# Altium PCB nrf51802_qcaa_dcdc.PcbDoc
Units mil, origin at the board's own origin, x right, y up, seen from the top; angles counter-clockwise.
Board outline 582.37 x 541 mil, 2 copper layers (Top Layer, Bottom Layer), stack 62.441 mil thick; 22 components, 32 nets, 78 pads, 39 vias.
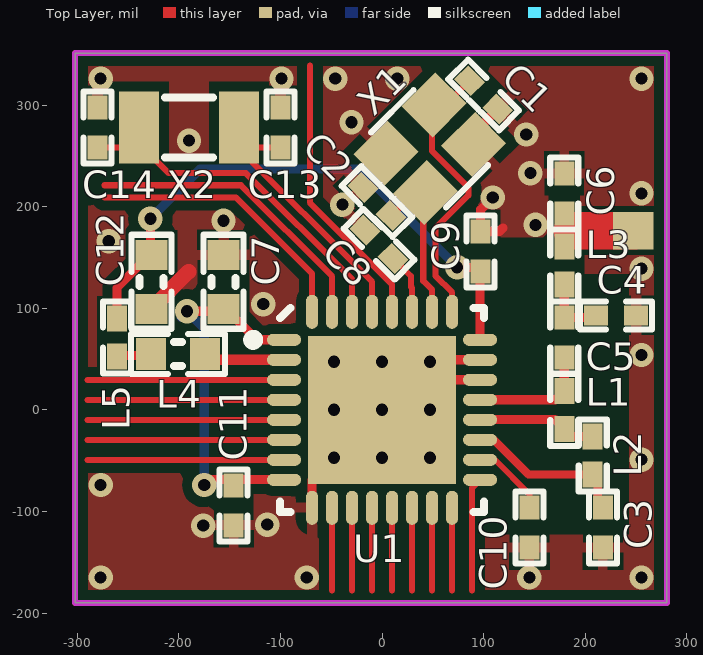
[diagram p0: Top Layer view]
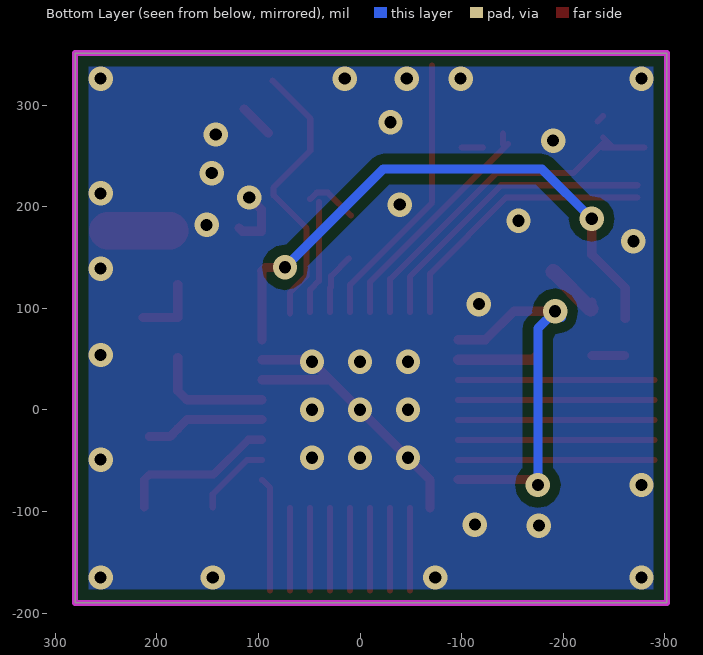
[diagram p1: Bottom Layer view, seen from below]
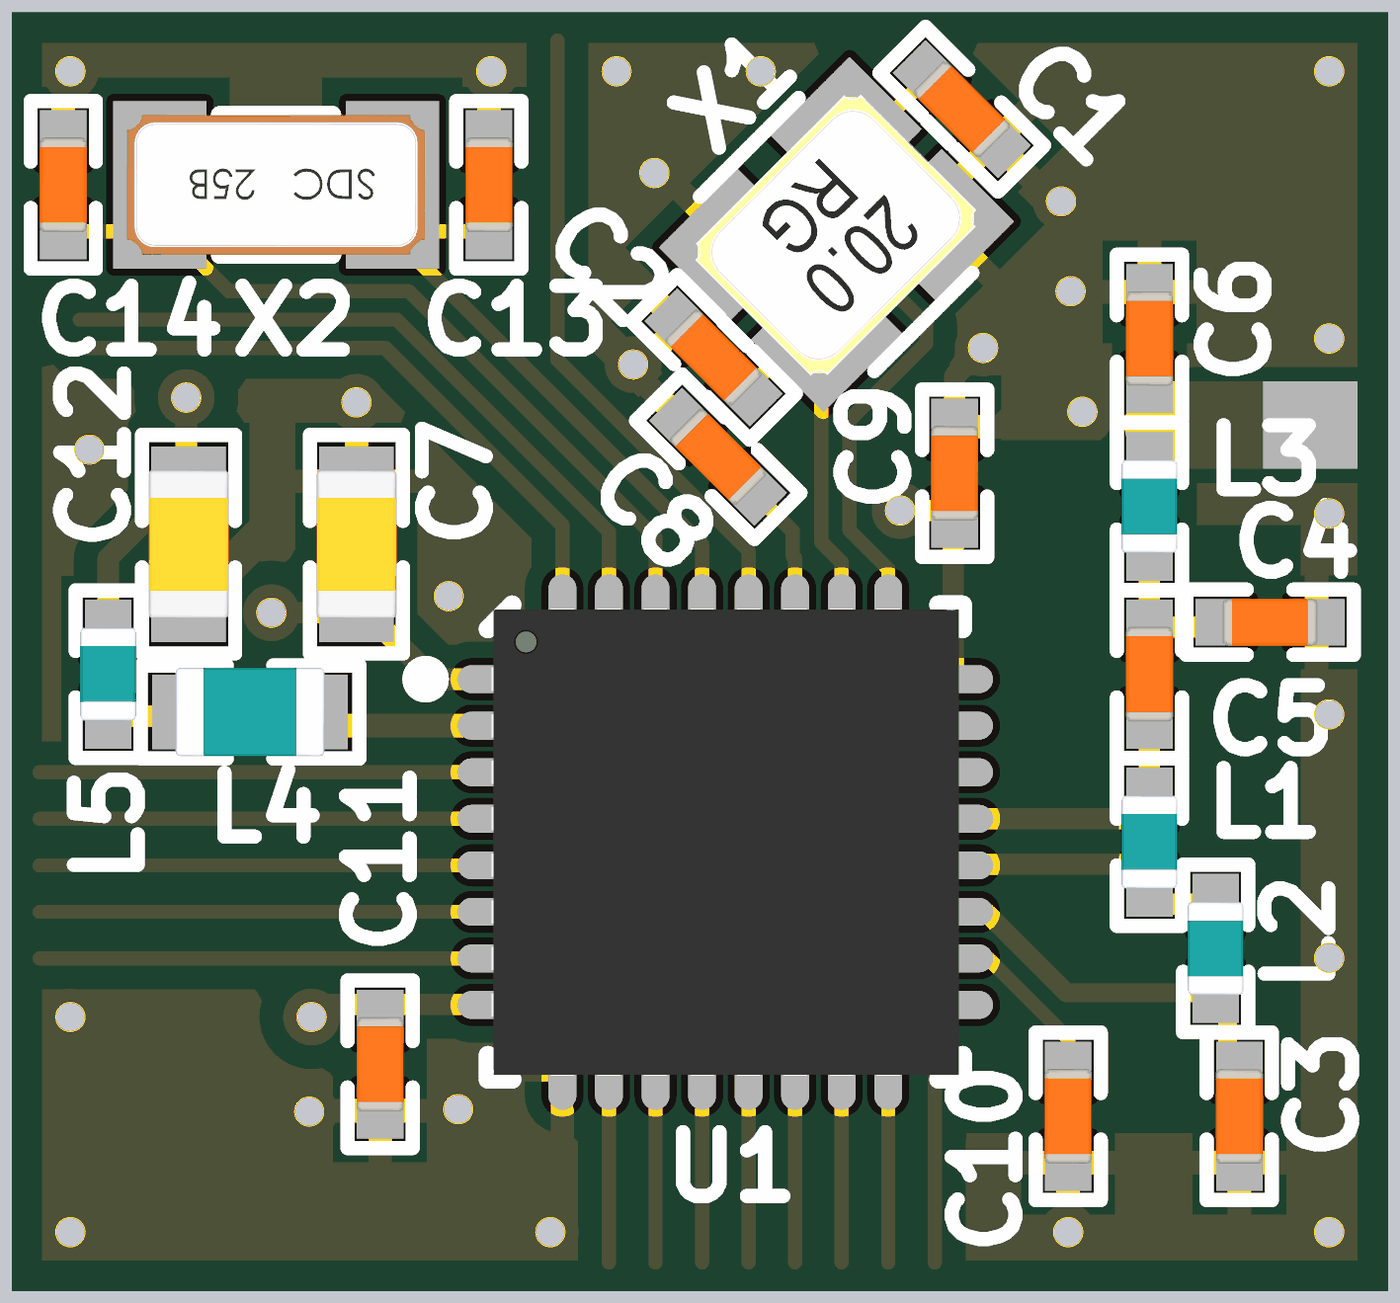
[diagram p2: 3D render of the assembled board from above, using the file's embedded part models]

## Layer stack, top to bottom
Top Solder: solder mask 0.4, Solder Resist, Dk 3.5
Top Layer: signal copper 0.7087
Dielectric1: core 61.0236, FR-4, Dk 4.8
Bottom Layer: signal copper 0.7087
Bottom Solder: solder mask 0.4, Solder Resist, Dk 3.5

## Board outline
-302,-190 280.37,-190 280.37,351 -302,351

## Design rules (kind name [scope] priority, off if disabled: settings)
Clearance Polygon_ANT [(InNamedPolygon('Top_Layer-GND')) or (InNamedPolygon('Bottom_Layer-GND')) vs InNet('NetC6_1')] p1: gap=6
Clearance Polygon [(InNamedPolygon('Top_Layer-GND')) or (InNamedPolygon('Bottom_Layer-GND'))] p2: gap=10
Clearance [All] p3: gap=6
ComponentClearance [All] p1 off: gap=10 collisioncheckmode=3 verticalgap=10 showdistances=FALSE
FabricationTestPointUsage TestPointUsage [All] p1: valid=0 allowmultiple=FALSE
FabricationTestpoint Testpoint [All] p1: side=3 testpointundercomponent=TRUE minsize=40 maxsize=100 preferedsize=60 minholesize=0 maxholesize=40 preferedholesize=32 testpointgrid=1 allowsidetop=TRUE allowsidebottom=TRUE usegrid=TRUE gridtolerance=0.01
Height [All] p1 off: minheight=0 maxheight=1000 prefheight=500
HoleSize [All] p1: absolutevalues=TRUE maxlimit=160 minlimit=12 maxpercent=80.000 minpercent=20.000
MinimumAnnularRing [All] p1 off: minimumring=6
PolygonConnect PolygonConnect_1 [isVia and innet(gnd)] p1: connectstyle=Direct reliefconductorwidth=10 reliefentries=4 polygonreliefangle="90 Angle" airgapwidth=10
PolygonConnect [All] p2: connectstyle=Relief reliefconductorwidth=10 reliefentries=4 polygonreliefangle="90 Angle" airgapwidth=10
RoutingVias [All] p1: holewidth=12 width=24 viastyle="Through Hole" minholewidth=12 minwidth=24 maxholewidth=28 maxwidth=50
SilkToSolderMaskClearance SilkscreenOverComponentPads [IsPad] p1: minsilkscreentomaskgap=10 clearancetoexposedcopper=TRUE
SolderMaskExpansion [All] p1: expansion=3
Width [All] p1: maxlimit=100 minlimit=6 preferedwidth=6
24 further rules are at their usual default settings.

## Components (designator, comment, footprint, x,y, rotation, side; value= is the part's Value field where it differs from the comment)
C1 "12pF" CAPC1005X04L 100,310 r315 top (schematic designator C7)
C2 "12pF" CAPC1005X04L -5,205 r135 top
C3 "2.2nF" CAPC1005X04L 217.37,-116 r270 top
C4 "1.0pF" CAPC1005X04L 230.37,93 r0 top
C5 "3.9pF" CAPC1005X04L 179.37,71 r90 top
C6 "1.5pF" CAPC1005X04L 179.37,213 r90 top
C7 "4.7µF" CAPC1608X06L -156,126 r90 top (schematic designator C9)
C8 "100nF" CAPC1005X04L -3,163 r135 top (schematic designator C10)
C9 "1.0nF" CAPC1005X04L 97,156 r90 top (schematic designator C8)
C10 "47nF" CAPC1005X04L 145,-116 r270 top (schematic designator C11)
C11 "100nF" CAPC1005X04L -146,-94 r270 top (schematic designator C12)
C12 "1.0µF" CAPC1608X06L -227,126 r90 top (schematic designator C11)
C13 "12pF" CAPC1005X04L -100,278 r270 top
C14 "12pF" CAPC1005X04L -280,278 r270 top
L1 "5.6nH" INDC1005X04L 179.37,0 r90 top
L2 "10nH" INDC1005X04L 207.37,-45 r90 top
L3 "2.7nH" INDC1005X04L 179.37,142 r90 top
L4 "10µH" INDC1608X06L -201,55 r180 top (schematic designator L5)
L5 "15nH" INDC1005X04L -261,71 r90 top (schematic designator L6)
U1 "nRF51802-QCAA" Nordic_QFN50P500X500X90-33N 0,0 r0 top
X1 "16MHz" BT-XTAL_2520 47,257 r225 top
X2 "32.768kHz" XTAL_3215 -190,278 r180 top

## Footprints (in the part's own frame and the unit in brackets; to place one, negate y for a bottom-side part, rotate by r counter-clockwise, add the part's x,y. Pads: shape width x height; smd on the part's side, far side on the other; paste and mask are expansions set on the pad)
BT-XTAL_2520 [mm] "TSX-2520"
  rect 1.2x1.1 smd: 1(-0.85,-0.7) 2(0.85,-0.7) 3(0.85,0.7) 4(-0.85,0.7)
  silkscreen extent -1.55,-1.33 1.53,1.32, body extent -1.25,-1 1.27,1, height 0.56
CAPC1005X04L [mm] "Chip Capacitor, 2-Leads, Body 1.0x0.5mm, IPC High Density"
  rect 0.6x0.5 smd: 1(-0.5,0) 2(0.5,0)
  silkscreen extent -0.9,-0.35 0.9,0.35, body extent -0.51,-0.25 0.51,0.25, height 0.5
CAPC1608X06L [mm] "Chip Capacitor, 2-Leads, Body 1.6x0.8mm, IPC High Density"
  rect 0.75x0.8 smd: 1(-0.675,0) 2(0.675,0)
  silkscreen extent -1.17,-0.5 1.17,0.5, body extent -0.8,-0.43 0.8,0.43, height 0.8
INDC1005X04L [mm] "Chip Inductor, 2-Leads, Body 1.0x0.5mm, IPC High Density"
  rect 0.65x0.5 smd: 1(-0.475,0) 2(0.475,0)
  silkscreen extent -0.9,-0.35 0.9,0.35, body extent -0.5,-0.3 0.5,0.3, height 0.5
INDC1608X06L [mm] "Chip Inductor, 2-Leads, Body 1.6x0.8mm, IPC High Density"
  rect 0.75x0.8 smd: 1(-0.675,0) 2(0.675,0)
  silkscreen extent -1.17,-0.5 1.17,0.5, body extent -0.8,-0.48 0.8,0.48, height 0.8
Nordic_QFN50P500X500X90-33N [mm] "QFN32 5x5x0.85mm, 0.5mm pitch - Medium Density"
  oval 0.85x0.3 smd mask+0.076: 1(-2.45,1.75) 2(-2.45,1.25) 3(-2.45,0.75) 4(-2.45,0.25) 5(-2.45,-0.25) 6(-2.45,-0.75) 7(-2.45,-1.25) 8(-2.45,-1.75) 17(2.45,-1.75) 18(2.45,-1.25) 19(2.45,-0.75) 20(2.45,-0.25) 21(2.45,0.25) 22(2.45,0.75) 23(2.45,1.25) 24(2.45,1.75)
  oval 0.3x0.85 smd mask+0.076: 9(-1.75,-2.45) 10(-1.25,-2.45) 11(-0.75,-2.45) 12(-0.25,-2.45) 13(0.25,-2.45) 14(0.75,-2.45) 15(1.25,-2.45) 16(1.75,-2.45) 25(1.75,2.45) 26(1.25,2.45) 27(0.75,2.45) 28(0.25,2.45) 29(-0.25,2.45) 30(-0.75,2.45) 31(-1.25,2.45) 32(-1.75,2.45)
  rect 3.7x3.7 smd mask+0: 33(0,0)
  silkscreen extent -3.34,-2.55 2.55,2.55, body extent -2.51,-2.51 2.51,2.51, height 0.8
XTAL_3215 [mm] "XTAL SMD 3.2 x 1.5 mm"
  rect 1x1.8 smd: 1(-1.25,0) 2(1.25,0)
  silkscreen extent -0.6,-0.75 0.6,0.75, body extent -1.6,-0.75 1.6,0.75, height 0.81

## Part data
C1 C2 C13 C14: library part C0402-12p, "Capacitor, NP0, ±2%"
C3: library part C0402-2n2, "Capacitor, X7R, ±10%"
C4: library part C0402-1.0p, "Capacitor, NP0, ±0.1pF"
C5: library part C0402-3.9p, "Capacitor, NP0, ±0.1pF"
C6: library part C0402-1.5p, "Capacitor, NP0, ±0.1pF"
C7: library part C0603-4µ7, "Capacitor, X5R, ±10%"
C8 C11: library part C0402-100n, "Capacitor, X7R, ±10%"
C9: library part C0402-1n0, "Capacitor, X7R, ±10%"
C10: library part C0402-47n, "Capacitor, X7R, ±10%"
C12: library part C0603-1µ0, "Capacitor, X7R, ±10%"
L1: library part L0402-5n6, "High frequency chip inductor ±5%"
L2: library part L0402-10n, "High frequency chip inductor ±5%"
L3: library part L0402-2n7, "Inductor, 220mA, ±0.1nH"
L4: library part L0603-10µ, "Chip inductor, IDC,min = 50 mA, ±20%"
L5: library part L0402-15n, "High frequency chip inductor ±10%"
U1: "Multi-protocol Bluetooth Low Energy and 2.4GHz proprietary system-on-chip"
X1: library part XTAL_SMD2520_16MHz_8pF_NDK, "XTAL SMD 2520, 16MHz, 8pF, ±40ppm"
X2: library part "XTAL_FC-135 32.768k", "XTAL SMD 3215, 32.768kHz, 9pF, ±20ppm"

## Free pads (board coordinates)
  rect 40x37 smd: 0(247.37,176.43)

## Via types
v1: diameter 24, hole 12, Top Layer to Bottom Layer, tented both sides, 30 vias
v2: diameter 24, hole 12, Top Layer to Bottom Layer, tented bottom, 9 vias

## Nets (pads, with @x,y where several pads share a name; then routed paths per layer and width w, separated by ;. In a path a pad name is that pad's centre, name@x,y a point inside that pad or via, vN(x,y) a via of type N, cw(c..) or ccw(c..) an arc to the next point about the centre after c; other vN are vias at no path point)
AVDD: C9.1 C12.2 L5.2 U1.24 | length 566.6
  Top Layer w9: L5.2 -261,120 -228,153 v1(-228,188) ; v1(73.91,140.24) 93.07,140.24 C9.1 96.46,135.77 U1.24
  Bottom Layer w9: v1(-228,188) -179,237 -22.85,237 v1(73.91,140.24)
GND: C1.2 C2.2 C3.2 C4.2 C6.2 C7.2 C8.2 C9.2 C10.2 C11.2 C12.1 C13.1 C14.1 U1.9 U1.22 U1.23 U1.33 X1.2 X1.4 | length 463.2
  Top Layer w9: C12.1@-228,99 C12.1@-228,106 ; U1.9 -68.9,-68.9 v2(-47.24,-47.24) v2(0,0) U1.33@29.53,29.53 ; X1.4@90.15,272.31 C1.2 ; U1.22 U1.33@29.53,29.53 ; U1.23 49.21,49.21 v2(47.24,47.24) U1.33@29.53,29.53 ; v1(109,209) 97,197 C9.2 115.69,175.69 119,179
  Top Layer w15: C12.1 -190.43,136 -190,136
  other v1: -277,-165 -74,-165 145,-165 255.37,-165 -176,-114 -113,-113 -277,-74 255.37,-49 255.37,54 -117,104 255.37,139 -269,166 151,182 -156,186 -39,202 255.37,213 146,233 -190,265 142,271 -30,283 -277,326 -99,326 -46,326 15,326 255.37,326
  other v2: 0,-47.24 47.24,-47.24 -47.24,0 47.24,0 -47.24,47.24 0,47.24
NetC1_1: C1.1 U1.25 X1.1 | length 279.4
  Top Layer w6: U1.25 68.9,115.55 52.53,131.92 52.53,178.53 85,211 85,219 49,255 49,286.84 C1.1 ; U1.25@69,95 U1.25@69,96.46
NetC2_1: C2.1 U1.26 X1.3 | length 164.1
  Top Layer w6: C2.1 31.69,213.85 X1.3 X1.3@49.21,207.46 ; X1.3@40.53,204.61 40.53,126.95 49.21,118.27 U1.26
NetC3_1: C3.1 L2.1 U1.19 | length 159.8
  Top Layer w8: U1.19 110.09,-29.53 144.27,-63.7 L2.1 212.37,-68.7 C3.1@212.37,-96.31
NetC4_1: C4.1 C5.2 L3.1 | length 66.6
  Top Layer w9: C5.2 L3.1 ; C5.2@179.68,91 C4.1@213.68,91
NetC5_1: C5.1 L1.2 U1.21 | length 119.2
  Top Layer w9: U1.21 170.51,9.84 L1.2 C5.1
NetC6_1: C6.1 L3.2 pad.0 | length 61
  Top Layer w37: 187.37,176.43 pad.0@248.37,176.43
NetC8_1: C8.1 U1.27 | length 60.3
  Top Layer w6: C8.1 28.53,131.47 28.53,121 29.53,120 U1.27
NetC10_1: C10.1 U1.18 | length 75.9
  Top Layer w6: U1.18 111.21,-49.21 145,-83 C10.1
NetL1_1: L1.1 L2.2 U1.20 | length 117.9
  Top Layer w9: U1.20@96.46,-9.37 170.04,-9.37 L1.1 186.97,-26.3 L2.2
NetL4_1: L4.1 U1.2 | length 79.1
  Top Layer w10: L4.1@-174,53 -170.21,49.21 U1.2
NetL4_2: L4.2 L5.1 | length 31.7
  Top Layer w9: L5.1@-259.98,53.32 L4.2@-228.32,53.32
P0.00: U1.3 | length 193.5
  Top Layer w6: -290,29.53 U1.3
P0.02: U1.4 | length 193.5
  Top Layer w6: -290,9.84 U1.4
P0.03: U1.5 | length 193.5
  Top Layer w6: -290,-9.84 U1.5
P0.04: U1.6 | length 193.5
  Top Layer w6: -290,-29.53 U1.6
P0.06: U1.7 | length 193.5
  Top Layer w6: -290,-49.21 U1.7
P0.08: U1.10 | length 81.4
  Top Layer w6: -49.21,-177.81 U1.10
P0.09: U1.11 | length 81.4
  Top Layer w6: -29.53,-177.81 U1.11
P0.12: U1.12 | length 81.4
  Top Layer w6: -9.84,-177.81 U1.12
P0.14: U1.13 | length 81.4
  Top Layer w6: 9.84,-177.81 U1.13
P0.16: U1.14 | length 81.4
  Top Layer w6: 29.53,-177.81 U1.14
P0.17: U1.17 | length 112.2
  Top Layer w6: 88.58,-177.81 88.58,-76.77 U1.17
P0.21: U1.28 | length 276
  Top Layer w6: -71,339 -71,204 9.84,123.16 U1.28
P0.28: U1.31 | length 295.8
  Top Layer w6: -273,221 -138.91,221 -49.21,131.3 U1.31
P0.29: U1.32 | length 272.7
  Top Layer w6: -273,209 -143.88,209 -68.9,134.02 U1.32
SWCLK: U1.16 | length 81.4
  Top Layer w6: 68.9,-177.81 U1.16
SWDIO: U1.15 | length 81.4
  Top Layer w6: 49.21,-177.81 U1.15
VCC_NRF: C7.1 C11.1 U1.1 U1.8 | length 374.5
  Top Layer w9: v1(-192,97) -151.48,97 -123.38,68.9 U1.1 ; v1(-175,-74) -169.61,-68.61 U1.8@-96.46,-68.61
  Bottom Layer w9: v1@-198,91 v1(-192,97) -175,80 v1(-175,-74)
XL1: C14.2 U1.30 X2.2 | length 363.5
  Top Layer w6: C14.2 X2.2@-248.9,258.31 ; X2.2@-239.21,268 X2.2@-248.9,258.31 ; X2.2@-239.21,289.21 X2.2@-233.61,283.61 ; U1.30 -29.53,128.59 -133.94,233 -210,233 -239.21,262.21 -239.21,258.31 X2.2@-248.9,258.31
XL2: C13.2 U1.29 X2.1 | length 253
  Top Layer w6: X2.1@-145.79,261.82 -9.84,125.87 U1.29 ; X2.1@-140.79,261.82 X2.1@-140.79,272 ; -121.1,258.31 C13.2

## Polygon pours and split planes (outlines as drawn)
GND on Bottom Layer "Bottom_Layer-GND" (solid, remove dead copper, pour order 1001): -321,400 -321,-266.19 293,-266.19 293,400 -321,400
GND on Top Layer "Top_Layer-GND" (solid, remove dead copper, pour order 5): -333,-278 -333,401.12 -331.7,405.06 302.73,405.06 304.35,410 304.35,-276.03 305,-278

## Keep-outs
Keep-Out Layer:
  the board outline again, w6

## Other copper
Top Layer:
  pour cut-out: 21.58,164.42 -5.03,137.82 -26.95,159.74 -0.34,186.34
  pour cut-out: 243.37,-123 102,-123 102,134 243.37,134
  pour cut-out: 199.37,107 86,107 86,170 199.37,170

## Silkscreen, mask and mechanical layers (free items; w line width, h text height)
Mechanical 1:
  the board outline again, w6

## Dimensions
280.37,351 to 280.37,-190 on Mechanical 3
-302,-190 to 280.37,-190 on Mechanical 3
